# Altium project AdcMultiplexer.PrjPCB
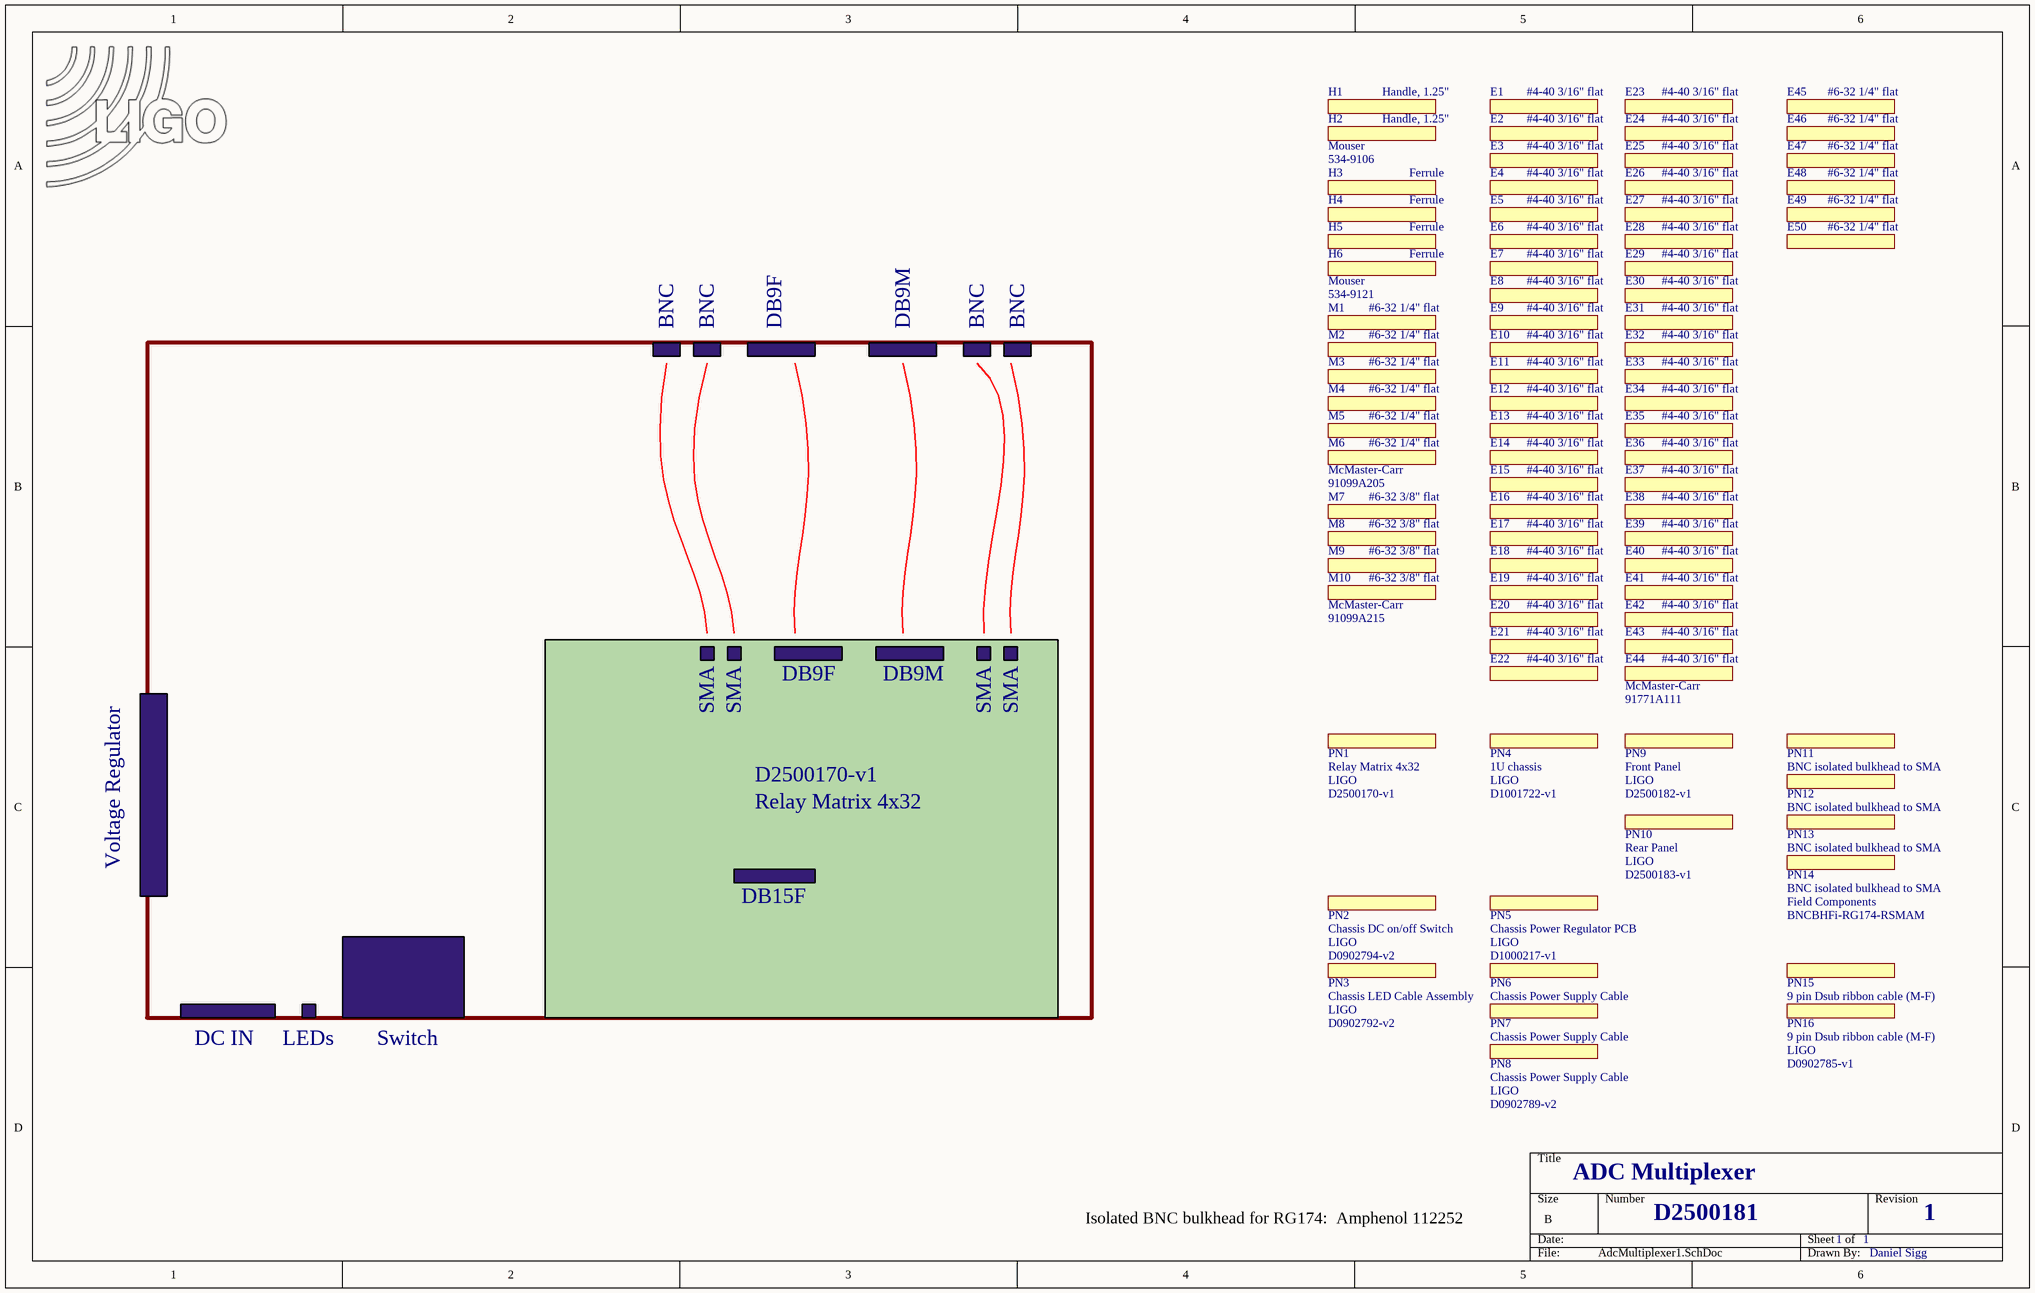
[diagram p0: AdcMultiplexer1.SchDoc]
REV: 1; DCC: D2500181
1 sheet, 83 parts. Net scope: global (net labels, ports and power ports of the same name join across sheets).

## Sheet AdcMultiplexer1.SchDoc: DAC Multiplexer
size B; Engineer: Daniel Sigg; DocumentNumber: D2500181; Revision: 1; SheetNumber: 1; SheetTotal: 1; PageSetup: Record=PageOptions¦CenterHorizontal=True¦CenterVertical=True¦PrintScale=1.12¦XCorrection=1.00¦YCorrection=1.00¦PrintKind=0¦BorderSize=5000000¦LeftOffset=0¦BottomOffset=0¦Orientation=2¦PaperLength=1000¦PaperWidth=1000¦Scale=100¦PaperSource=7¦PrintQuality=-4¦MediaType=1¦DitherType=10¦PaperKind=11 x 17¦PrintScaleMode=1

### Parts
E1  #4-40 3/16" flat  (mechanical)
E2  #4-40 3/16" flat  (mechanical)
E3  #4-40 3/16" flat  (mechanical)
E4  #4-40 3/16" flat  (mechanical)
E5  #4-40 3/16" flat  (mechanical)
E6  #4-40 3/16" flat  (mechanical)
E7  #4-40 3/16" flat  (mechanical)
E8  #4-40 3/16" flat  (mechanical)
E9  #4-40 3/16" flat  (mechanical)
E10  #4-40 3/16" flat  (mechanical)
E11  #4-40 3/16" flat  (mechanical)
E12  #4-40 3/16" flat  (mechanical)
E13  #4-40 3/16" flat  (mechanical)
E14  #4-40 3/16" flat  (mechanical)
E15  #4-40 3/16" flat  (mechanical)
E16  #4-40 3/16" flat  (mechanical)
E17  #4-40 3/16" flat  (mechanical)
E18  #4-40 3/16" flat  (mechanical)
E19  #4-40 3/16" flat  (mechanical)
E20  #4-40 3/16" flat  (mechanical)
E21  #4-40 3/16" flat  (mechanical)
E22  #4-40 3/16" flat  (mechanical)
E23  #4-40 3/16" flat  (mechanical)
E24  #4-40 3/16" flat  (mechanical)
E25  #4-40 3/16" flat  (mechanical)
E26  #4-40 3/16" flat  (mechanical)
E27  #4-40 3/16" flat  (mechanical)
E28  #4-40 3/16" flat  (mechanical)
E29  #4-40 3/16" flat  (mechanical)
E30  #4-40 3/16" flat  (mechanical)
E31  #4-40 3/16" flat  (mechanical)
E32  #4-40 3/16" flat  (mechanical)
E33  #4-40 3/16" flat  (mechanical)
E34  #4-40 3/16" flat  (mechanical)
E35  #4-40 3/16" flat  (mechanical)
E36  #4-40 3/16" flat  (mechanical)
E37  #4-40 3/16" flat  (mechanical)
E38  #4-40 3/16" flat  (mechanical)
E39  #4-40 3/16" flat  (mechanical)
E40  #4-40 3/16" flat  (mechanical)
E41  #4-40 3/16" flat  (mechanical)
E42  #4-40 3/16" flat  (mechanical)
E43  #4-40 3/16" flat  (mechanical)
E44  #4-40 3/16" flat  Part Number: 91771A111  Distributor: McMaster-Carr  (mechanical)
E45  #6-32 1/4" flat  (mechanical)
E46  #6-32 1/4" flat  (mechanical)
E47  #6-32 1/4" flat  (mechanical)
E48  #6-32 1/4" flat  (mechanical)
E49  #6-32 1/4" flat  (mechanical)
E50  #6-32 1/4" flat  (mechanical)
H1  Handle, 1.25"  (mechanical)
H2  Handle, 1.25"  Part Number: 534-9106  Distributor: Mouser  (mechanical)
H3  Ferrule  (mechanical)
H4  Ferrule  (mechanical)
H5  Ferrule  (mechanical)
H6  Ferrule  Part Number: 534-9121  Distributor: Mouser  (mechanical)
LOGO1  LIGO logo  [LIGO_LOGO]  (value not drawn)  (no BOM)
M1  #6-32 1/4" flat  (mechanical)
M2  #6-32 1/4" flat  (mechanical)
M3  #6-32 1/4" flat  (mechanical)
M4  #6-32 1/4" flat  (mechanical)
M5  #6-32 1/4" flat  (mechanical)
M6  #6-32 1/4" flat  Part Number: 91099A205  Distributor: McMaster-Carr  (mechanical)
M7  #6-32 3/8" flat  (mechanical)
M8  #6-32 3/8" flat  (mechanical)
M9  #6-32 3/8" flat  (mechanical)
M10  #6-32 3/8" flat  Part Number: 91099A215  Distributor: McMaster-Carr  (mechanical)
PN1  Relay Matrix 4x32  Part Number: D2500170-v1  Distributor: LIGO  (mechanical)
PN2  Chassis DC on/off Switch  Part Number: D0902794-v2  Distributor: LIGO  (mechanical)
PN3  Chassis LED Cable Assembly  Part Number: D0902792-v2  Distributor: LIGO  (mechanical)
PN4  1U chassis  Part Number: D1001722-v1  Distributor: LIGO  (mechanical)
PN5  Chassis Power Regulator PCB  Part Number: D1000217-v1  Distributor: LIGO  (mechanical)
PN6  Chassis Power Supply Cable  (mechanical)
PN7  Chassis Power Supply Cable  (mechanical)
PN8  Chassis Power Supply Cable  Part Number: D0902789-v2  Distributor: LIGO  (mechanical)
PN9  Front Panel  Part Number: D2500182-v1  Distributor: LIGO  (mechanical)
PN10  Rear Panel  Part Number: D2500183-v1  Distributor: LIGO  (mechanical)
PN11  BNC isolated bulkhead to SMA  (mechanical)
PN12  BNC isolated bulkhead to SMA  (mechanical)
PN13  BNC isolated bulkhead to SMA  (mechanical)
PN14  BNC isolated bulkhead to SMA  Part Number: BNCBHFi-RG174-RSMAM  Distributor: Field Components  (mechanical)
PN15  9 pin Dsub ribbon cable (M-F)  (mechanical)
PN16  9 pin Dsub ribbon cable (M-F)  Part Number: D0902785-v1  Distributor: LIGO  (mechanical)

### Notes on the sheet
- BNC
- DB9F
- DB9M
- SMA
- Relay Matrix 4x32
- D2500170-v1
- Voltage Regulator
- DB15F
- DC IN
- LEDs
- Switch
- ADC Multiplexer
- Isolated BNC bulkhead for RG174:  Amphenol 112252
- 1
- Daniel Sigg

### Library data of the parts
E1-E43 = Partlist: #4-40 3/16" flat head screw; Part Number: 91771A111
E44 = Partlist: #4-40 3/16" flat head screw
E45-E50 M1-M5 = Partlist: #6-32 1/4" flat head screw; Part Number: 91099A205
H1 = Partlist: Rack handle; Part Number: 534-9106
H2 = Partlist: Rack handle
H3-H5 = Partlist: Part Number: 534-9121
H6 = Partlist
LOGO1 = LIGO_logo
M6 = Partlist: #6-32 1/4" flat head screw
M7-M9 = Partlist: #6-32 3/8" flat head screw; Part Number: 91099A215
M10 = Partlist: #6-32 3/8" flat head screw
PN1 = Partlist: PCB
PN2-PN5 PN8 PN14 PN16 = Partlist: chassis
PN6 PN7 = Partlist: chassis; Part Number: D0902789-v2
PN9 PN10 = Partlist: panel
PN11-PN13 = Partlist: chassis; Part Number: BNCBHFi-RG174-RSMAM
PN15 = Partlist: chassis; Part Number: D0902785-v1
